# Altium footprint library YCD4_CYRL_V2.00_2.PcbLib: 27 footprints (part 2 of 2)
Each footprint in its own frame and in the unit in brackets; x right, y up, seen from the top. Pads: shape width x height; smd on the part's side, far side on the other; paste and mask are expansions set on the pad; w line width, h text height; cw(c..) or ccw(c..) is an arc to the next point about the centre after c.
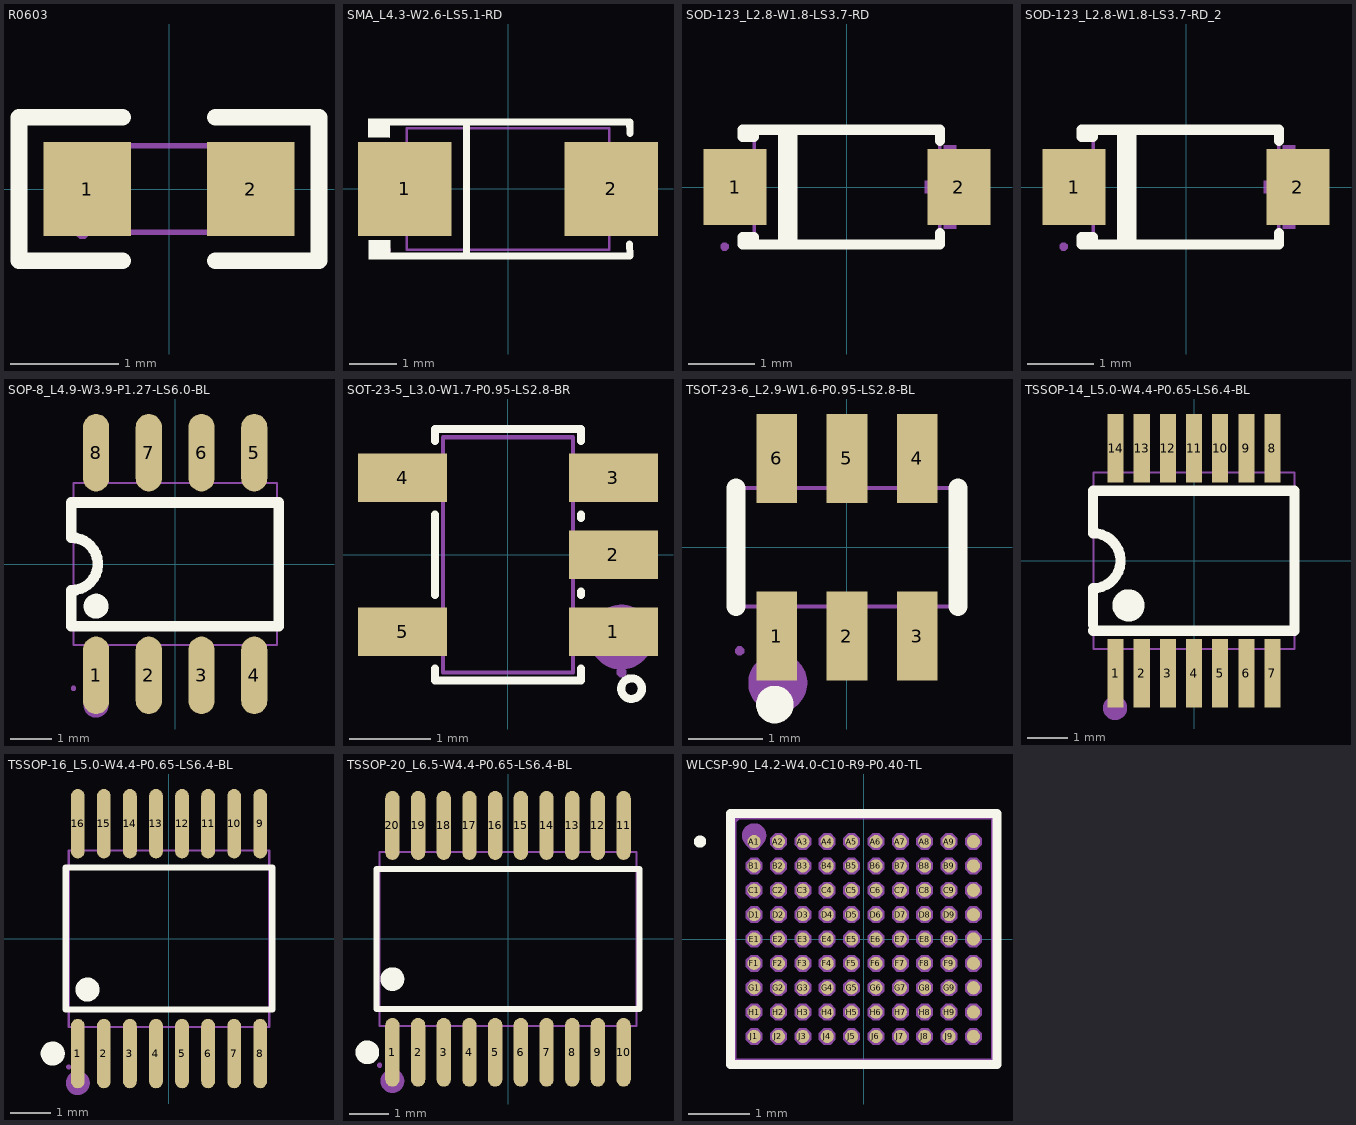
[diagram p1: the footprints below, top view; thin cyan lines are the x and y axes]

## R0603 [mm]
pads (2):
  rect 0.806x0.864 smd paste-100 mask+0.051: 1(-0.753,0) 2(0.753,0)
Top Overlay:
  lines w0.152: -0.426,-0.661 -1.385,-0.661 -1.385,0.661 -0.426,0.661 ; 0.426,-0.661 1.385,-0.661 1.385,0.661 0.426,0.661
Top Paste:
  region: -1.195,-0.45 -0.395,-0.45 -0.345,-0.4 -0.345,-0.172 -0.715,-0.172 -0.715,0.158 -0.345,0.158 -0.345,0.4 -0.395,0.45 -1.195,0.45 -1.245,0.4 -1.245,-0.4
  region: 1.195,0.45 0.395,0.45 0.345,0.4 0.345,0.172 0.715,0.172 0.715,-0.158 0.345,-0.158 0.345,-0.4 0.395,-0.45 1.195,-0.45 1.245,-0.4 1.245,0.4
Mechanical 15:
  region: 0.8,-0.4 0.8,0.4 0.5,0.4 0.5,-0.4
  region: -0.8,-0.4 -0.8,0.4 -0.5,0.4 -0.5,-0.4
  region: -0.74,-0.4 -0.74,-0.375 -0.775,-0.34 -0.825,-0.34 -0.86,-0.375 -0.86,-0.4 -0.86,-0.425 -0.825,-0.46 -0.775,-0.46 -0.74,-0.425 -0.74,-0.4
  lines w0.051: -0.8,-0.4 0.8,-0.4 0.8,0.4 -0.8,0.4 -0.8,-0.4
3D body: height 0.5, standoff 0, extent -0.753,-0.4 0.847,0.4

## SMA_L4.3-W2.6-LS5.1-RD [mm]
pads (2):
  rect 2x2 smd: 1(-2.2,0) 2(2.2,0)
Top Overlay:
  region: -2.52,1.502 -2.521,1.096 -2.981,1.1 -2.977,1.502
  region: -2.512,-1.096 -2.513,-1.503 -2.973,-1.498 -2.969,-1.096
  lines w0.152: -2.596,-1.426 2.596,-1.426 ; -2.596,1.426 2.596,1.426 2.603,1.187 ; -0.884,-1.426 -0.884,1.426 ; 2.593,-1.176 2.6,-1.415
Mechanical 6:
  region: -2.317,-0.101 -2.317,0.101 -1.507,0.101 -1.507,-0.101
  region: 2.317,-0.101 2.317,0.101 1.507,0.101 1.507,-0.101
  region: 2.014,-0.675 2.014,0.675 1.811,0.675 1.811,-0.675
Mechanical 15:
  region: 2.56,0.725 2.56,-0.725 1.435,-0.725 1.435,0.725
  region: -1.435,0.725 -1.435,-0.725 -2.56,-0.725 -2.56,0.725
  region: -2.5,-1.3 -2.501,-1.276 -2.536,-1.243 -2.584,-1.243 -2.619,-1.276 -2.62,-1.3 -2.619,-1.324 -2.584,-1.357 -2.536,-1.357 -2.501,-1.324 -2.5,-1.3
  lines w0.051: -2.16,-1.3 2.16,-1.3 2.16,1.3 -2.16,1.3 -2.16,-1.3
3D body: height 2.3, standoff 0, extent -2.16,-1.3 2.16,1.3

## SOD-123_L2.8-W1.8-LS3.7-RD [mm]
pads (2):
  rect 0.95x1.15 smd: 1(-1.692,0) 2(1.692,0)
Top Overlay:
  lines w0.152: -0.97,-0.866 -0.97,0.866 ; -0.827,-0.866 -0.827,0.866 ; 1.406,-0.698 1.406,-0.866 -1.406,-0.866 ; 1.406,0.698 1.406,0.866 -1.406,0.866 ; -1.406,-0.866 -1.406,-0.755 -1.58,-0.755 -1.58,-0.866 -1.406,-0.866 ; -1.406,0.866 -1.406,0.755 -1.58,0.755 -1.58,0.866 -1.406,0.866
Mechanical 6:
  region: 1.651,0.635 1.651,-0.629 1.461,-0.629 1.461,0.635
  region: 1.935,0.098 1.935,-0.092 1.177,-0.092 1.177,0.098
  region: -2.03,0.095 -2.03,-0.095 -1.272,-0.095 -1.272,0.095
Mechanical 15:
  region: 1.851,-0.465 1.851,0.465 1.301,0.465 1.301,-0.465
  region: -1.851,-0.465 -1.851,0.465 -1.301,0.465 -1.301,-0.465
  region: -1.79,-0.9 -1.79,-0.875 -1.826,-0.84 -1.875,-0.84 -1.91,-0.875 -1.91,-0.9 -1.91,-0.925 -1.875,-0.96 -1.826,-0.96 -1.79,-0.925 -1.79,-0.9
  lines w0.051: -1.4,-0.9 1.4,-0.9 1.4,0.9 -1.4,0.9 -1.4,-0.9
3D body: height 1.35, standoff 0, extent -1.4,-0.9 1.4,0.9

## SOD-123_L2.8-W1.8-LS3.7-RD_2 [mm]
pads (2):
  rect 0.95x1.15 smd: 1(-1.692,0) 2(1.692,0)
Top Overlay:
  lines w0.152: -0.97,-0.866 -0.97,0.866 ; -0.827,-0.866 -0.827,0.866 ; 1.406,-0.698 1.406,-0.866 -1.406,-0.866 ; 1.406,0.698 1.406,0.866 -1.406,0.866 ; -1.406,-0.866 -1.406,-0.755 -1.58,-0.755 -1.58,-0.866 -1.406,-0.866 ; -1.406,0.866 -1.406,0.755 -1.58,0.755 -1.58,0.866 -1.406,0.866
Mechanical 6:
  region: 1.651,0.635 1.651,-0.629 1.461,-0.629 1.461,0.635
  region: 1.935,0.098 1.935,-0.092 1.177,-0.092 1.177,0.098
  region: -2.03,0.095 -2.03,-0.095 -1.272,-0.095 -1.272,0.095
Mechanical 15:
  region: 1.851,-0.465 1.851,0.465 1.301,0.465 1.301,-0.465
  region: -1.851,-0.465 -1.851,0.465 -1.301,0.465 -1.301,-0.465
  region: -1.79,-0.9 -1.79,-0.875 -1.826,-0.84 -1.875,-0.84 -1.91,-0.875 -1.91,-0.9 -1.91,-0.925 -1.875,-0.96 -1.826,-0.96 -1.79,-0.925 -1.79,-0.9
  lines w0.051: -1.4,-0.9 1.4,-0.9 1.4,0.9 -1.4,0.9 -1.4,-0.9

## SOP-8_L4.9-W3.9-P1.27-LS6.0-BL [mm]
pads (8):
  oval 0.63x1.865 smd: 1(-1.905,-2.682) 2(-0.635,-2.682) 3(0.635,-2.682) 4(1.905,-2.682) 5(1.905,2.682) 6(0.635,2.682) 7(-0.635,2.682) 8(-1.905,2.682)
Top Overlay:
  circle w0.3: c-1.905,-1.016 r0.15
  lines w0.254: -2.5,-1.498 -2.5,-0.635 ccw(c-2.5,0) -2.499,0.635 -2.499,1.482 2.5,1.482 2.5,-1.498 -2.5,-1.498
Mechanical 6:
  circle w0.3: c-1.905,-3.4 r0.15
Mechanical 15:
  region: -2.39,-3 -2.39,-2.975 -2.425,-2.94 -2.475,-2.94 -2.51,-2.975 -2.51,-3 -2.51,-3.025 -2.475,-3.06 -2.425,-3.06 -2.39,-3.025 -2.39,-3
  region: 1.695,2.165 1.695,3 2.115,3 2.115,2.165
  region: 0.425,2.165 0.425,3 0.845,3 0.845,2.165
  region: -0.845,2.165 -0.845,3 -0.425,3 -0.425,2.165
  region: -2.115,2.165 -2.115,3 -1.695,3 -1.695,2.165
  region: 1.695,-3 1.695,-2.165 2.115,-2.165 2.115,-3
  region: 0.425,-3 0.425,-2.165 0.845,-2.165 0.845,-3
  region: -0.845,-3 -0.845,-2.165 -0.425,-2.165 -0.425,-3
  region: -2.115,-3 -2.115,-2.165 -1.695,-2.165 -1.695,-3
  region: 1.695,2.232 2.115,2.232 2.115,1.942 1.695,1.942
  region: 0.425,2.232 0.845,2.232 0.845,1.942 0.425,1.942
  region: -0.845,2.232 -0.425,2.232 -0.425,1.942 -0.845,1.942
  region: -2.115,2.232 -1.695,2.232 -1.695,1.942 -2.115,1.942
  region: -1.695,-2.232 -2.115,-2.232 -2.115,-1.942 -1.695,-1.942
  region: -0.425,-2.232 -0.845,-2.232 -0.845,-1.942 -0.425,-1.942
  region: 0.845,-2.232 0.425,-2.232 0.425,-1.942 0.845,-1.942
  region: 2.115,-2.232 1.695,-2.232 1.695,-1.942 2.115,-1.942
  lines w0.051: -2.45,-1.95 -2.45,1.95 2.45,1.95 2.45,-1.95 -2.45,-1.95
3D body: height 0.9, standoff 0, extent -2.46,-1.959 2.46,1.975

## SOT-23-5_L3.0-W1.7-P0.95-LS2.8-BR [mm]
pads (5):
  rect 1.1x0.6 smd: 1(1.3,-0.95) 2(1.3,0) 3(1.3,0.95) 4(-1.3,0.95) 5(-1.3,-0.95)
Top Overlay:
  circle w0.1: c1.524,-1.651 r0.127
  lines w0.1: -0.9,-1.404 -0.9,-1.55 0.9,-1.55 0.9,-1.404 ; -0.9,-0.496 -0.9,0.496 ; -0.9,1.404 -0.9,1.55 0.9,1.55 0.9,1.404 ; 0.9,-0.496 0.9,-0.454 ; 0.9,0.454 0.9,0.496
Mechanical 6:
  circle w0.4: c1.397,-1.016 r0.2
Mechanical 15:
  region: -1.4,-1.15 -1.4,-0.75 -0.95,-0.75 -0.95,-1.15
  region: -0.96,-1.15 -0.96,-0.75 -0.79,-0.75 -0.79,-1.15
  region: -1.4,0.75 -1.4,1.15 -0.95,1.15 -0.95,0.75
  region: -0.96,0.75 -0.96,1.15 -0.79,1.15 -0.79,0.75
  region: 0.95,0.75 0.95,1.15 1.4,1.15 1.4,0.75
  region: 0.79,0.75 0.79,1.15 0.96,1.15 0.96,0.75
  region: 0.95,-0.2 0.95,0.2 1.4,0.2 1.4,-0.2
  region: 0.79,-0.2 0.79,0.2 0.96,0.2 0.96,-0.2
  region: 0.95,-1.15 0.95,-0.75 1.4,-0.75 1.4,-1.15
  region: 0.79,-1.15 0.79,-0.75 0.96,-0.75 0.96,-1.15
  region: 1.46,-1.45 1.459,-1.426 1.424,-1.392 1.376,-1.392 1.341,-1.426 1.34,-1.45 1.341,-1.475 1.376,-1.508 1.424,-1.508 1.459,-1.474 1.46,-1.45
  lines w0.051: -0.8,-1.45 -0.8,1.45 0.8,1.45 0.8,-1.45 -0.8,-1.45
3D body: height 1.25, standoff 0, extent -0.805,-1.461 0.805,1.46

## TSOT-23-6_L2.9-W1.6-P0.95-LS2.8-BL [mm]
pads (6):
  rect 0.55x1.2 smd: 1(-0.95,-1.2) 2(0,-1.2) 3(0.95,-1.2) 4(0.95,1.2) 5(0,1.2) 6(-0.95,1.2)
Top Overlay:
  circle w0.254: c-0.975,-2.125 r0.127
  lines w0.254: -1.5,-0.8 -1.5,0.8 ; 1.5,-0.8 1.5,0.8
Mechanical 6:
  circle w0.4: c-0.934,-1.832 r0.2
Mechanical 15:
  region: -1.39,-1.4 -1.39,-1.375 -1.425,-1.34 -1.475,-1.34 -1.51,-1.375 -1.51,-1.4 -1.51,-1.425 -1.475,-1.46 -1.425,-1.46 -1.39,-1.425 -1.39,-1.4
  region: -1.137,1 -1.137,1.4 -0.762,1.4 -0.762,1
  region: -1.137,0.79 -1.137,1.01 -0.762,1.01 -0.762,0.79
  region: 0.762,1 0.762,1.4 1.137,1.4 1.137,1
  region: 0.762,0.79 0.762,1.01 1.137,1.01 1.137,0.79
  region: 0.762,-1.4 0.762,-1 1.137,-1 1.137,-1.4
  region: 0.762,-1.01 0.762,-0.79 1.137,-0.79 1.137,-1.01
  region: -0.188,-1.4 -0.188,-1 0.188,-1 0.188,-1.4
  region: -0.187,-1.01 -0.188,-0.79 0.188,-0.79 0.188,-1.01
  region: -1.137,-1.4 -1.137,-1 -0.762,-1 -0.762,-1.4
  region: -1.137,-1.01 -1.137,-0.79 -0.762,-0.79 -0.762,-1.01
  region: -0.188,1 -0.188,1.4 0.188,1.4 0.188,1
  region: -0.188,0.79 -0.188,1.01 0.188,1.01 0.188,0.79
  lines w0.051: -1.45,-0.8 -1.45,0.8 1.45,0.8 1.45,-0.8 -1.45,-0.8
3D body: height 1.1, standoff 0, extent -1.502,-0.809 1.397,0.804

## TSSOP-14_L5.0-W4.4-P0.65-LS6.4-BL [mm]
pads (14):
  rect 0.4x1.7 smd: 1(-1.95,-2.8) 2(-1.3,-2.8) 3(-0.65,-2.8) 4(0,-2.8) 5(0.65,-2.8) 6(1.3,-2.8) 7(1.95,-2.8) 8(1.95,2.8) 9(1.3,2.8) 10(0.65,2.8) 11(0,2.8) 12(-0.65,2.8) 13(-1.3,2.8) 14(-1.95,2.8)
Top Overlay:
  circle w0.4: c-1.63,-1.11 r0.2
  lines w0.254: -2.515,-1.74 2.5,-1.74 2.5,1.743 -2.515,1.743 -2.515,0.686 cw(c-2.515,0) -2.515,-0.686 -2.515,-1.6
Mechanical 6:
  circle w0.3: c-1.964,-3.662 r0.15
Mechanical 15:
  drawing of 33 lines, arcs and shapes, not listed
3D body: height 1.2, standoff 0, extent -2.509,-2.197 2.494,2.192

## TSSOP-16_L5.0-W4.4-P0.65-LS6.4-BL [mm]
pads (16):
  oval 0.343x1.731 smd: 1(-2.275,-2.866) 2(-1.625,-2.866) 3(-0.975,-2.866) 4(-0.325,-2.866) 5(0.325,-2.866) 6(0.975,-2.866) 7(1.625,-2.866) 8(2.275,-2.866) 9(2.275,2.866) 10(1.625,2.866) 11(0.975,2.866) 12(0.325,2.866) 13(-0.325,2.866) 14(-0.975,2.866) 15(-1.625,2.866) 16(-2.275,2.866)
Top Overlay:
  circle w0.3: c-2.032,-1.27 r0.15
  circle w0.3: c-2.899,-2.866 r0.15
  lines w0.152: -2.576,-1.771 -2.576,1.772 2.576,1.772 2.576,-1.771 -2.576,-1.771
Mechanical 6:
  circle w0.3: c-2.275,-3.6 r0.15
Mechanical 15:
  drawing of 37 lines, arcs and shapes, not listed
3D body: height 1.2, standoff 0, extent -2.499,-2.2 2.508,2.21

## TSSOP-20_L6.5-W4.4-P0.65-LS6.4-BL [mm]
pads (20):
  oval 0.364x1.742 smd: 1(-2.925,-2.871) 2(-2.275,-2.871) 3(-1.625,-2.871) 4(-0.975,-2.871) 5(-0.325,-2.871) 6(0.325,-2.871) 7(0.975,-2.871) 8(1.625,-2.871) 9(2.275,-2.871) 10(2.925,-2.871) 11(2.925,2.871) 12(2.275,2.871) 13(1.625,2.871) 14(0.975,2.871) 15(0.325,2.871) 16(-0.325,2.871) 17(-0.975,2.871) 18(-1.625,2.871) 19(-2.275,2.871) 20(-2.925,2.871)
Top Overlay:
  circle w0.3: c-3.559,-2.871 r0.15
  circle w0.3: c-2.925,-1.019 r0.15
  lines w0.152: -3.326,-1.771 3.326,-1.771 3.326,1.771 -3.326,1.771 -3.326,-1.771
Mechanical 6:
  circle w0.3: c-2.925,-3.6 r0.15
Mechanical 15:
  drawing of 45 lines, arcs and shapes, not listed
3D body: height 2.65, standoff 0, extent -3.262,-2.189 3.25,2.201

## WLCSP-90_L4.2-W4.0-C10-R9-P0.40-TL [mil]
pads (90):
  round 8.5 smd paste-3937 mask+2: A1(-70.87,62.99) A2(-55.12,62.99) A3(-39.37,62.99) A4(-23.62,62.99) A5(-7.87,62.99) A6(7.87,62.99) A7(23.62,62.99) A8(39.37,62.99) A9(55.12,62.99) A10(70.87,62.99) B1(-70.87,47.24) B2(-55.12,47.24) B3(-39.37,47.24) B4(-23.62,47.24) B5(-7.87,47.24) B6(7.87,47.24) B7(23.62,47.24) B8(39.37,47.24) B9(55.12,47.24) B10(70.87,47.24) C1(-70.87,31.5) C2(-55.12,31.5) C3(-39.37,31.5) C4(-23.62,31.5) C5(-7.87,31.5) C6(7.87,31.5) C7(23.62,31.5) C8(39.37,31.5) C9(55.12,31.5) C10(70.87,31.5) D1(-70.87,15.75) D2(-55.12,15.75) D3(-39.37,15.75) D4(-23.62,15.75) D5(-7.87,15.75) D6(7.87,15.75) D7(23.62,15.75) D8(39.37,15.75) D9(55.12,15.75) D10(70.87,15.75) E1(-70.87,0) E2(-55.12,0) E3(-39.37,0) E4(-23.62,0) E5(-7.87,0) E6(7.87,0) E7(23.62,0) E8(39.37,0) E9(55.12,0) E10(70.87,0) F1(-70.87,-15.75) F2(-55.12,-15.75) F3(-39.37,-15.75) F4(-23.62,-15.75) F5(-7.87,-15.75) F6(7.87,-15.75) F7(23.62,-15.75) F8(39.37,-15.75) F9(55.12,-15.75) F10(70.87,-15.75) G1(-70.87,-31.5) G2(-55.12,-31.5) G3(-39.37,-31.5) G4(-23.62,-31.5) G5(-7.87,-31.5) G6(7.87,-31.5) G7(23.62,-31.5) G8(39.37,-31.5) G9(55.12,-31.5) G10(70.87,-31.5) H1(-70.87,-47.24) H2(-55.12,-47.24) H3(-39.37,-47.24) H4(-23.62,-47.24) H5(-7.87,-47.24) H6(7.87,-47.24) H7(23.62,-47.24) H8(39.37,-47.24) H9(55.12,-47.24) H10(70.87,-47.24) J1(-70.87,-62.99) J2(-55.12,-62.99) J3(-39.37,-62.99) J4(-23.62,-62.99) J5(-7.87,-62.99) J6(7.87,-62.99) J7(23.62,-62.99) J8(39.37,-62.99) J9(55.12,-62.99) J10(70.87,-62.99)
Top Overlay:
  circle w3.94: c-105.81,62.99 r1.97
  lines w6: -86.13,-81.13 86.13,-81.13 86.13,81.13 -86.13,81.13 -86.13,-81.13
Top Paste:
  drawing of 90 lines, arcs and shapes, not listed
Mechanical 6:
  circle w7.87: c-70.87,66.93 r3.94
Mechanical 15:
  drawing of 95 lines, arcs and shapes, not listed
3D body: height 23.62, standoff 0, extent -85,-80 85,80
